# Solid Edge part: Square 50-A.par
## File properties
Title: Square 50 x 46 Cm da incasso
Author: DESYS
Template: Normal.par
Last saved by: PIM_1
Revision: 14
Application: Solid Edge
Tipo di contenuto documento: 0
Precisione: 0,990
Document Number: 8025/A
Revision: 0
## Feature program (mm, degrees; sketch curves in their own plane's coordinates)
sketch for "unnamed Protrusion 1" plane through (0, 0, 0) normal (0, 0, 1) x-axis (1, 0, 0)
  line (-255, -230) -> (255, -230)
  line (255, -230) -> (255, 230)
  line (255, 230) -> (-255, 230)
  line (-255, 230) -> (-255, -230)
extrude "unnamed Protrusion 1" add finite 160 along -normal
sketch for "ExtrudedCutout_1" plane through (0, -185, -80) normal (0, -1, 0) x-axis (1, 0, 0)
  arc centre (0, 240.125) radius 260.125 from (-205, 80) to (205, 80) ccw
extrude "ExtrudedCutout_1" cut finite 275 along -normal  Profile_Plane1_Distance = 45 mm
sketch for "ExtrudedCutout_2" plane through (0, 0, -160) normal (0, 0, -1) x-axis (1, 0, 0)
  line (240, -120) -> (240, 210)
  line (-240, 210) -> (240, 210)
  line (-240, 210) -> (-240, -120)
  line (-240, -120) -> (240, -120)
extrude "ExtrudedCutout_2" cut finite 75 along -normal
sketch for "ExtrudedCutout_3" plane through (0, -55, -160) normal (0, 0, -1) x-axis (1, 0, 0)
  line (-190, -260) -> (190, -260)
  line (190, -260) -> (190, -155)
  line (190, -155) -> (-190, -155)
  line (-190, -155) -> (-190, -260)
extrude "ExtrudedCutout_3" cut finite 145 along -normal
sketch for "ExtrudedCutout_4" plane through (0, 100, -87.5) normal (0, 1, 0) x-axis (1, 0, 0)
  line (-165.3054, 72.5) -> (-151.1429, 18.2575)
  arc centre (-145.3375, 19.7733) radius 6 from (-151.1429, 18.2575) to (-143.8985, 13.9484) ccw
  arc centre (0, -568.5404) radius 600 from (-143.8985, 13.9484) to (143.8985, 13.9484) cw
  arc centre (145.3375, 19.7733) radius 6 from (143.8985, 13.9484) to (151.1429, 18.2575) ccw
  line (165.3054, 72.5) -> (151.1429, 18.2575)
extrude "ExtrudedCutout_4" cut finite 265 along -normal
sketch for "unnamed Protrusion 2" plane through (0, -55, -160) normal (0, 0, -1) x-axis (0, -1, 0)
  circle centre (5, 0) radius 35
extrude "unnamed Protrusion 2" add through along -normal
sketch for "Foro_1" plane through (0, 10, -160) normal (0, 0, -1) x-axis (0, -1, 0)
  hole centre (70, 0) bore radius 22.5
hole "Foro_1" diameter 45 through
draft "Draft_1"  Angles1 = 10 deg
sketch for "Foro_2" plane through (0, 0, 0) normal (0, 0, 1) x-axis (0, -1, 0)
  hole centre (-160, 0) bore radius 17.5
hole "Foro_2" diameter 35 through
sketch for "unnamed Protrusion 3" plane through (0, 0, 0) normal (1, 0, 0) x-axis (0, 1, 0)
  line (-25, -154.4516) -> (106.5927, -142.4478)
  arc centre (104.7759, -122.5305) radius 20 from (106.5927, -142.4478) to (124.5661, -125.4193) ccw
  line (124.5661, -125.4193) -> (140.6961, -14.9172)
extrude "unnamed Protrusion 3" add to key point symmetric
fillet "Rotondo_1" radius 5
fillet "Rotondo_2" radius 10
fillet "Rotondo_3" radius 2
fillet "Rotondo_4" radius 10
fillet "Rotondo_5" radius 10
fillet "Rotondo_7" radius 5
fillet "Rotondo_8" radius 5
fillet "Rotondo_9" radius 5
fillet "Rotondo_10" radius 10
sketch for "Foro_3" plane through (0, 0, 0) normal (0, -1, 0) x-axis (1, 0, 0)
  hole centre (0, -25) bore radius 10
hole "Foro_3" diameter 20 finite
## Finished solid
Body 1: solid body, 163 faces, 350 edges, 189 vertices.
  Faces by surface: cylinder 76, blend 31, plane 30, sphere 19, torus 7
  Edges by curve: line 143, circle 128, ellipse 55, intersection 24
Bounding box of the edges (mm; curved faces can reach further): 510.000 x 460.000 x 160.000, from (-255, -230, -160) to (255, 230, 0).
Cylindrical faces by radius (mm): R5 x29, R6 x2, R10 x39, R17.5 x1, R20 x1, R22.5 x1, R35 x1, R260.125 x1, R600 x1
Toroidal faces (ring radius, tube radius in mm): R10 r5 x2, R15 r5 x2, R19.5 r2 x1, R30 r5 x1, R610 r10 x1
Spherical faces by radius (mm): R5 x11, R10 x8
Planar faces by outward normal: +x 3, +y 3, +z 1, -x 3, -y 4, -z 5, oblique 11
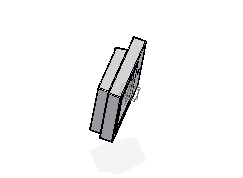
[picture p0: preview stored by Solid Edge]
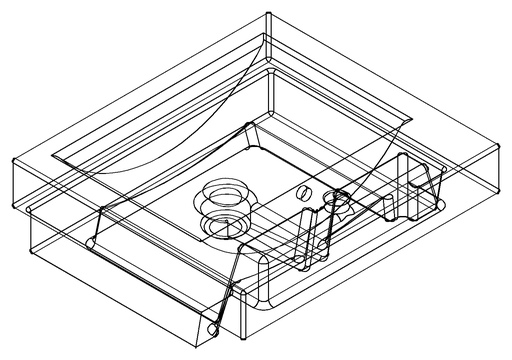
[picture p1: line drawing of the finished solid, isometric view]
